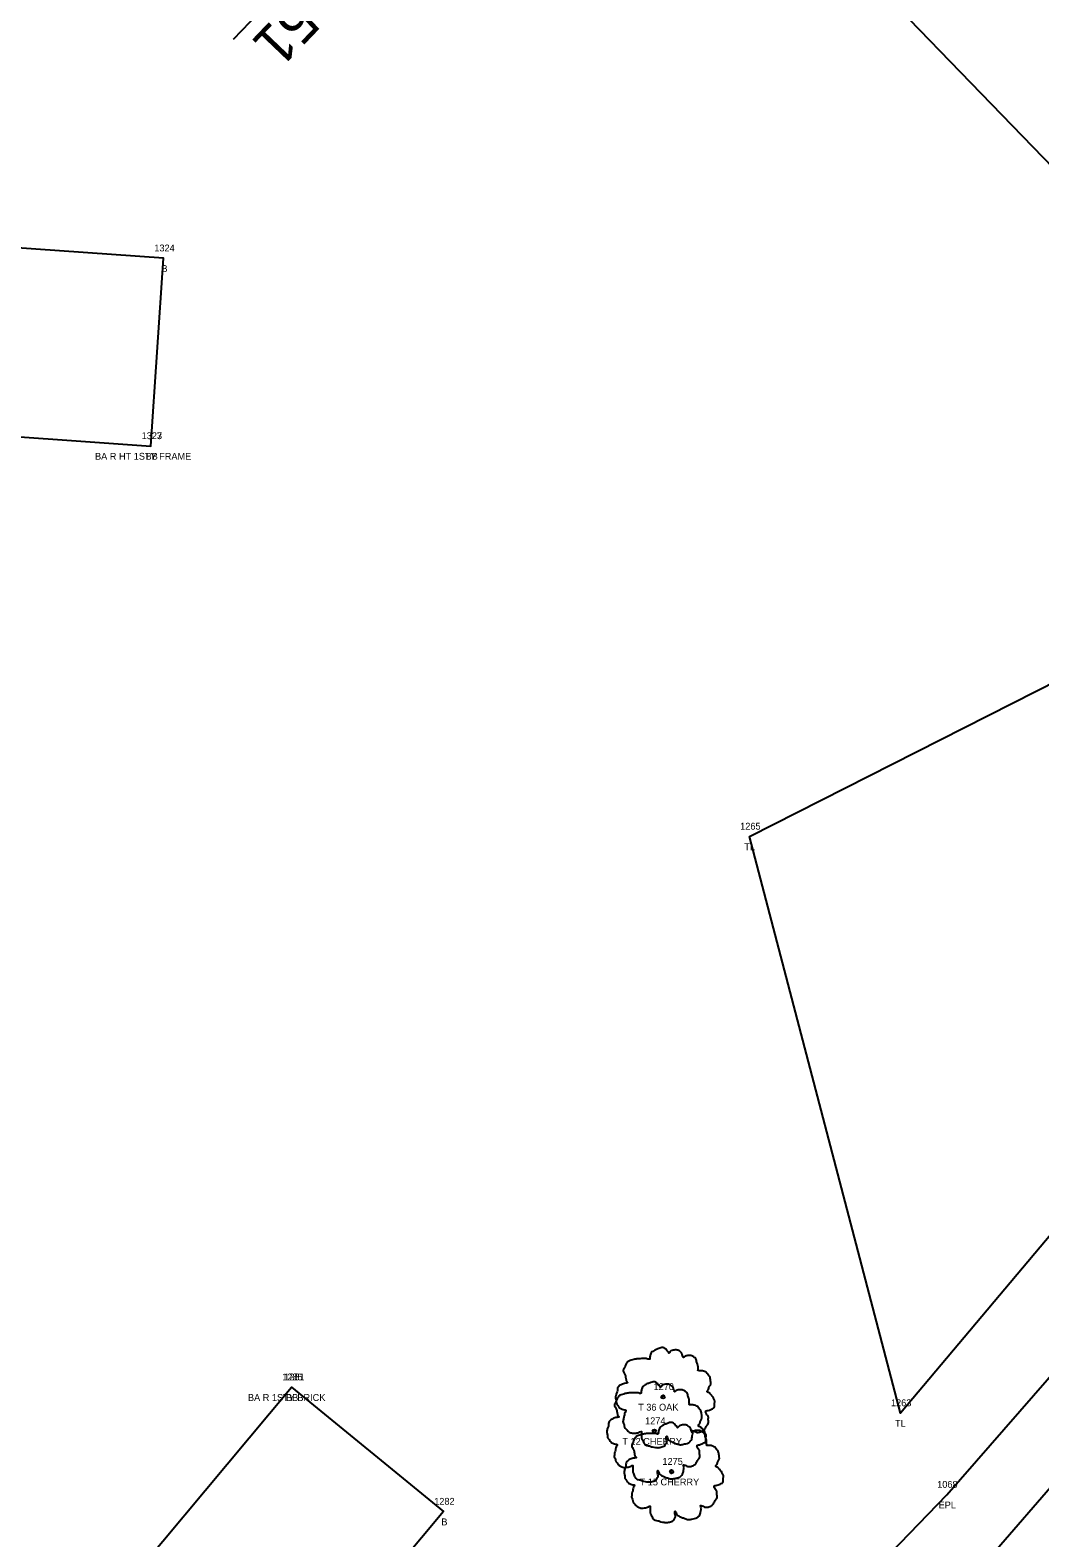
# Model space of a CAD drawing. Extents: x 1812340 to 1815011, y 1177659 to 1180159.
# Drawn here: x 1813776.3 to 1813923.6, y 1178289.1 to 1178509 of the extents above; entities that cross this region are included whole.
import ezdxf

# ---------------------------------------------------------------- set-up
doc = ezdxf.new("R2010")
doc.units = 0
for name, color, linetype in [('RD_EX_Bldg', 7, 'Continuous'), ('RD_EX_Bldg_txCode', 7, 'Continuous'), ('RD_EX_Road', 7, 'Continuous'), ('RD_EX_Road_txCode', 7, 'Continuous'), ('RD_EX_VEG', 7, 'Continuous'), ('RD_EX_VEG_txCode', 7, 'Continuous'), ('RD_HC_CL', 7, 'Continuous'), ('RD_HC_Data', 7, 'Continuous'), ('RD_SMD_Locator', 7, 'Continuous')]:
    doc.layers.add(name, color=color, linetype=linetype)

msp = doc.modelspace()

# ---------------------------------------------------------------- linework, layer by layer
at = {"layer": 'RD_EX_Bldg'}
for points in [[(1813793.91, 1178448.32), (1813795.75, 1178475.7), (1813735.04, 1178479.99), (1813733.19, 1178452.61), (1813793.91, 1178448.32)], [(1813814.41, 1178311.05), (1813836.59, 1178292.91), (1813805.22, 1178255.39), (1813783.05, 1178273.53), (1813814.41, 1178311.05)]]:
    msp.add_lwpolyline(points, dxfattribs=at)
at = {"layer": 'RD_EX_Road'}
msp.add_lwpolyline([(1813829.87, 1178208.6), (1813830.81, 1178209.56), (1813845.51, 1178227.94), (1813874.69, 1178258.74), (1813910.02, 1178295.38), (1813943.63, 1178333.84), (1813974.31, 1178373.09), (1814001.91, 1178410.56), (1814011.9, 1178425.95), (1814015.58, 1178434.3), (1814016.71, 1178442.08), (1814017.03, 1178447.13), (1814015.19, 1178453.67), (1813986.47, 1178480.85), (1813949.15, 1178515.86)], dxfattribs=at)
at = {"layer": 'RD_EX_VEG'}
for points in [[(1813964.65, 1178448.48), (1813984.61, 1178463.55), (1813943.71, 1178503.46), (1813904.65, 1178537.57), (1813863.79, 1178578.71), (1813833.99, 1178603.93), (1813823.24, 1178594.53), (1813964.65, 1178448.48)], [(1813961.33, 1178431.97), (1813986.04, 1178406.55), (1813953.31, 1178366.71), (1813903.24, 1178307.28), (1813881.24, 1178391.37), (1813961.33, 1178431.97)]]:
    msp.add_lwpolyline(points, dxfattribs=at)
for centre, radius in [((1813868.62, 1178309.64), 0.25), ((1813868.61, 1178309.62), 0.0001), ((1813867.35, 1178304.65), 0.25), ((1813867.34, 1178304.63), 0.0001), ((1813869.87, 1178298.73), 0.25), ((1813869.86, 1178298.71), 0.0001)]:
    msp.add_circle(centre, radius, dxfattribs=at)
for points in [[(1813868.75, 1178316.81), (1813868.45, 1178316.83), (1813868.13, 1178316.73), (1813867.88, 1178316.63), (1813867.65, 1178316.56), (1813867.43, 1178316.46), (1813867.13, 1178316.28), (1813866.9, 1178316.08), (1813866.78, 1178315.83), (1813866.73, 1178315.61), (1813866.68, 1178315.33), (1813866.68, 1178315.16), (1813866.55, 1178315.13), (1813866.4, 1178315.16), (1813866.15, 1178315.23), (1813865.9, 1178315.23), (1813865.65, 1178315.23), (1813865.3, 1178315.21), (1813864.95, 1178315.21), (1813864.68, 1178315.16), (1813864.35, 1178315.11), (1813863.98, 1178314.98), (1813863.63, 1178314.86), (1813863.33, 1178314.61), (1813863.08, 1178314.13), (1813862.96, 1178313.78), (1813862.81, 1178313.53), (1813862.96, 1178313.08), (1813863.13, 1178312.73), (1813863.15, 1178312.53), (1813863.23, 1178312.11), (1813863.33, 1178311.88), (1813863.45, 1178311.68), (1813863.38, 1178311.66), (1813863.01, 1178311.61), (1813862.71, 1178311.51), (1813862.28, 1178311.28), (1813862.06, 1178311.06), (1813861.96, 1178310.73), (1813861.93, 1178310.38), (1813861.83, 1178310.18), (1813861.76, 1178309.91), (1813861.73, 1178309.83), (1813861.68, 1178309.51), (1813861.78, 1178309.06), (1813861.81, 1178308.71), (1813861.93, 1178308.49), (1813862.08, 1178308.31), (1813862.26, 1178308.06), (1813862.66, 1178307.84), (1813862.98, 1178307.74), (1813863.18, 1178307.71), (1813863.01, 1178307.21), (1813862.96, 1178306.86), (1813862.83, 1178306.46), (1813862.83, 1178306.39), (1813862.78, 1178305.91), (1813862.93, 1178305.59), (1813863.01, 1178305.21), (1813863.18, 1178304.99), (1813863.45, 1178304.69), (1813863.78, 1178304.46), (1813864.28, 1178304.34), (1813864.68, 1178304.36), (1813865.25, 1178304.54), (1813865.5, 1178304.61), (1813865.48, 1178304.44), (1813865.5, 1178304.06), (1813865.5, 1178303.64), (1813865.65, 1178303.31), (1813865.75, 1178303.04), (1813865.9, 1178302.79), (1813866.23, 1178302.56), (1813866.63, 1178302.49), (1813867.05, 1178302.34), (1813867.5, 1178302.26), (1813868, 1178302.24), (1813868.6, 1178302.39), (1813868.88, 1178302.51), (1813868.98, 1178302.69), (1813869.18, 1178303.06), (1813869.13, 1178303.29), (1813869.15, 1178303.89), (1813869.25, 1178303.71), (1813869.43, 1178303.36), (1813869.93, 1178303.06), (1813870.33, 1178302.89), (1813870.8, 1178302.74), (1813871.1, 1178302.66), (1813871.58, 1178302.74), (1813871.95, 1178302.81), (1813872.33, 1178302.94), (1813872.63, 1178303.21), (1813872.8, 1178303.49), (1813872.85, 1178303.76), (1813872.93, 1178304.14), (1813872.98, 1178304.31)], [(1813872.98, 1178304.31), (1813872.9, 1178304.49), (1813872.85, 1178304.74), (1813872.93, 1178304.71), (1813873.1, 1178304.66), (1813873.38, 1178304.54), (1813873.6, 1178304.46), (1813873.93, 1178304.49), (1813874.2, 1178304.59), (1813874.65, 1178304.86), (1813874.92, 1178305.34), (1813875.2, 1178305.74), (1813875.27, 1178306.06), (1813875.22, 1178306.29), (1813875.2, 1178306.79), (1813875, 1178307.04), (1813874.95, 1178307.16), (1813874.85, 1178307.56), (1813874.92, 1178307.61), (1813875.2, 1178307.66), (1813875.57, 1178307.79), (1813875.85, 1178307.91), (1813876.07, 1178308.09), (1813876.15, 1178308.31), (1813876.12, 1178308.71), (1813876.17, 1178309.11), (1813876.1, 1178309.26), (1813876, 1178309.41), (1813875.92, 1178309.61), (1813875.77, 1178309.76), (1813875.67, 1178309.91), (1813875.57, 1178310.01), (1813875.45, 1178310.16), (1813875.27, 1178310.28), (1813875.12, 1178310.33), (1813875.07, 1178310.48), (1813875.22, 1178310.68), (1813875.27, 1178310.78), (1813875.3, 1178311.01), (1813875.52, 1178311.36), (1813875.57, 1178311.76), (1813875.52, 1178312.18), (1813875.47, 1178312.46), (1813875.32, 1178312.73), (1813875.12, 1178312.98), (1813875, 1178313.16), (1813874.82, 1178313.28), (1813874.5, 1178313.41), (1813874.25, 1178313.46), (1813873.9, 1178313.46), (1813873.7, 1178313.51), (1813873.73, 1178313.56), (1813873.73, 1178313.71), (1813873.73, 1178313.98), (1813873.65, 1178314.43), (1813873.5, 1178314.93), (1813873.5, 1178314.96), (1813873.4, 1178315.21), (1813873.18, 1178315.41), (1813873, 1178315.51), (1813872.8, 1178315.63), (1813872.55, 1178315.66), (1813872.25, 1178315.66), (1813871.98, 1178315.61), (1813871.78, 1178315.51), (1813871.6, 1178315.38), (1813871.53, 1178315.53), (1813871.43, 1178315.83), (1813871.38, 1178315.98), (1813871.23, 1178316.16), (1813871, 1178316.36), (1813870.55, 1178316.48), (1813869.93, 1178316.41), (1813869.63, 1178316.21), (1813869.48, 1178316.03), (1813869.43, 1178316.16), (1813869.23, 1178316.36), (1813869.13, 1178316.53), (1813868.95, 1178316.66), (1813868.8, 1178316.76), (1813868.7, 1178316.81)], [(1813867.48, 1178311.82), (1813867.18, 1178311.84), (1813866.86, 1178311.74), (1813866.61, 1178311.64), (1813866.38, 1178311.57), (1813866.16, 1178311.47), (1813865.86, 1178311.29), (1813865.63, 1178311.09), (1813865.51, 1178310.84), (1813865.46, 1178310.62), (1813865.41, 1178310.34), (1813865.41, 1178310.17), (1813865.28, 1178310.14), (1813865.13, 1178310.17), (1813864.88, 1178310.24), (1813864.63, 1178310.24), (1813864.38, 1178310.24), (1813864.03, 1178310.22), (1813863.68, 1178310.22), (1813863.41, 1178310.17), (1813863.08, 1178310.12), (1813862.71, 1178309.99), (1813862.36, 1178309.87), (1813862.06, 1178309.62), (1813861.81, 1178309.14), (1813861.68, 1178308.79), (1813861.53, 1178308.54), (1813861.68, 1178308.09), (1813861.86, 1178307.74), (1813861.88, 1178307.54), (1813861.96, 1178307.12), (1813862.06, 1178306.89), (1813862.18, 1178306.69), (1813862.11, 1178306.67), (1813861.73, 1178306.62), (1813861.43, 1178306.52), (1813861.01, 1178306.29), (1813860.78, 1178306.07), (1813860.68, 1178305.74), (1813860.66, 1178305.39), (1813860.56, 1178305.19), (1813860.48, 1178304.92), (1813860.46, 1178304.84), (1813860.41, 1178304.52), (1813860.51, 1178304.07), (1813860.53, 1178303.72), (1813860.66, 1178303.5), (1813860.81, 1178303.32), (1813860.98, 1178303.07), (1813861.38, 1178302.85), (1813861.71, 1178302.75), (1813861.91, 1178302.72), (1813861.73, 1178302.22), (1813861.68, 1178301.87), (1813861.56, 1178301.47), (1813861.56, 1178301.4), (1813861.51, 1178300.92), (1813861.66, 1178300.6), (1813861.73, 1178300.22), (1813861.91, 1178300), (1813862.18, 1178299.7), (1813862.51, 1178299.47), (1813863.01, 1178299.35), (1813863.41, 1178299.37), (1813863.98, 1178299.55), (1813864.23, 1178299.62), (1813864.21, 1178299.45), (1813864.23, 1178299.07), (1813864.23, 1178298.65), (1813864.38, 1178298.32), (1813864.48, 1178298.05), (1813864.63, 1178297.8), (1813864.96, 1178297.57), (1813865.36, 1178297.5), (1813865.78, 1178297.35), (1813866.23, 1178297.27), (1813866.73, 1178297.25), (1813867.33, 1178297.4), (1813867.61, 1178297.52), (1813867.71, 1178297.7), (1813867.91, 1178298.07), (1813867.86, 1178298.3), (1813867.88, 1178298.9), (1813867.98, 1178298.72), (1813868.15, 1178298.37), (1813868.65, 1178298.07), (1813869.05, 1178297.9), (1813869.53, 1178297.75), (1813869.83, 1178297.67), (1813870.3, 1178297.75), (1813870.68, 1178297.82), (1813871.05, 1178297.95), (1813871.35, 1178298.22), (1813871.53, 1178298.5), (1813871.58, 1178298.77), (1813871.65, 1178299.15), (1813871.7, 1178299.32)], [(1813871.7, 1178299.32), (1813871.63, 1178299.5), (1813871.58, 1178299.75), (1813871.65, 1178299.72), (1813871.83, 1178299.67), (1813872.1, 1178299.55), (1813872.33, 1178299.47), (1813872.65, 1178299.5), (1813872.93, 1178299.6), (1813873.38, 1178299.87), (1813873.65, 1178300.35), (1813873.93, 1178300.75), (1813874, 1178301.07), (1813873.95, 1178301.3), (1813873.93, 1178301.8), (1813873.73, 1178302.05), (1813873.68, 1178302.17), (1813873.58, 1178302.57), (1813873.65, 1178302.62), (1813873.93, 1178302.67), (1813874.3, 1178302.8), (1813874.58, 1178302.92), (1813874.8, 1178303.1), (1813874.88, 1178303.32), (1813874.85, 1178303.72), (1813874.9, 1178304.12), (1813874.83, 1178304.27), (1813874.73, 1178304.42), (1813874.65, 1178304.62), (1813874.5, 1178304.77), (1813874.4, 1178304.92), (1813874.3, 1178305.02), (1813874.18, 1178305.17), (1813874, 1178305.29), (1813873.85, 1178305.34), (1813873.8, 1178305.49), (1813873.95, 1178305.69), (1813874, 1178305.79), (1813874.03, 1178306.02), (1813874.25, 1178306.37), (1813874.3, 1178306.77), (1813874.25, 1178307.19), (1813874.2, 1178307.47), (1813874.05, 1178307.74), (1813873.85, 1178307.99), (1813873.73, 1178308.17), (1813873.55, 1178308.29), (1813873.23, 1178308.42), (1813872.98, 1178308.47), (1813872.63, 1178308.47), (1813872.43, 1178308.52), (1813872.45, 1178308.57), (1813872.45, 1178308.72), (1813872.45, 1178308.99), (1813872.38, 1178309.44), (1813872.23, 1178309.94), (1813872.23, 1178309.97), (1813872.13, 1178310.22), (1813871.9, 1178310.42), (1813871.73, 1178310.52), (1813871.53, 1178310.64), (1813871.28, 1178310.67), (1813870.98, 1178310.67), (1813870.7, 1178310.62), (1813870.5, 1178310.52), (1813870.33, 1178310.39), (1813870.25, 1178310.54), (1813870.15, 1178310.84), (1813870.1, 1178310.99), (1813869.95, 1178311.17), (1813869.73, 1178311.37), (1813869.28, 1178311.49), (1813868.65, 1178311.42), (1813868.35, 1178311.22), (1813868.2, 1178311.04), (1813868.15, 1178311.17), (1813867.95, 1178311.37), (1813867.86, 1178311.54), (1813867.68, 1178311.67), (1813867.53, 1178311.77), (1813867.43, 1178311.82)], [(1813870.01, 1178305.89), (1813869.71, 1178305.92), (1813869.38, 1178305.82), (1813869.13, 1178305.72), (1813868.91, 1178305.64), (1813868.68, 1178305.54), (1813868.38, 1178305.37), (1813868.16, 1178305.17), (1813868.03, 1178304.92), (1813867.98, 1178304.69), (1813867.93, 1178304.42), (1813867.93, 1178304.25), (1813867.81, 1178304.22), (1813867.66, 1178304.25), (1813867.41, 1178304.32), (1813867.16, 1178304.32), (1813866.91, 1178304.32), (1813866.56, 1178304.3), (1813866.21, 1178304.3), (1813865.93, 1178304.25), (1813865.61, 1178304.2), (1813865.23, 1178304.07), (1813864.88, 1178303.95), (1813864.58, 1178303.7), (1813864.33, 1178303.22), (1813864.21, 1178302.87), (1813864.06, 1178302.62), (1813864.21, 1178302.17), (1813864.38, 1178301.82), (1813864.41, 1178301.62), (1813864.48, 1178301.2), (1813864.58, 1178300.97), (1813864.71, 1178300.77), (1813864.63, 1178300.75), (1813864.26, 1178300.7), (1813863.96, 1178300.6), (1813863.53, 1178300.37), (1813863.31, 1178300.15), (1813863.21, 1178299.82), (1813863.18, 1178299.47), (1813863.08, 1178299.27), (1813863.01, 1178299), (1813862.98, 1178298.92), (1813862.93, 1178298.6), (1813863.03, 1178298.15), (1813863.06, 1178297.8), (1813863.18, 1178297.57), (1813863.33, 1178297.4), (1813863.51, 1178297.15), (1813863.91, 1178296.92), (1813864.23, 1178296.82), (1813864.43, 1178296.8), (1813864.26, 1178296.3), (1813864.21, 1178295.95), (1813864.08, 1178295.55), (1813864.08, 1178295.47), (1813864.03, 1178295), (1813864.18, 1178294.67), (1813864.26, 1178294.3), (1813864.43, 1178294.07), (1813864.71, 1178293.77), (1813865.03, 1178293.55), (1813865.53, 1178293.42), (1813865.93, 1178293.45), (1813866.51, 1178293.62), (1813866.76, 1178293.7), (1813866.73, 1178293.52), (1813866.76, 1178293.15), (1813866.76, 1178292.73), (1813866.91, 1178292.4), (1813867.01, 1178292.13), (1813867.16, 1178291.88), (1813867.48, 1178291.65), (1813867.88, 1178291.58), (1813868.31, 1178291.43), (1813868.76, 1178291.35), (1813869.26, 1178291.33), (1813869.86, 1178291.48), (1813870.13, 1178291.6), (1813870.23, 1178291.78), (1813870.43, 1178292.15), (1813870.38, 1178292.38), (1813870.41, 1178292.98), (1813870.51, 1178292.8), (1813870.68, 1178292.45), (1813871.18, 1178292.15), (1813871.58, 1178291.98), (1813872.05, 1178291.83), (1813872.35, 1178291.75), (1813872.83, 1178291.83), (1813873.2, 1178291.9), (1813873.58, 1178292.03), (1813873.88, 1178292.3), (1813874.05, 1178292.58), (1813874.1, 1178292.85), (1813874.18, 1178293.22), (1813874.23, 1178293.4)], [(1813874.23, 1178293.4), (1813874.15, 1178293.57), (1813874.1, 1178293.82), (1813874.18, 1178293.8), (1813874.35, 1178293.75), (1813874.63, 1178293.62), (1813874.85, 1178293.55), (1813875.18, 1178293.57), (1813875.45, 1178293.67), (1813875.9, 1178293.95), (1813876.18, 1178294.42), (1813876.45, 1178294.82), (1813876.53, 1178295.15), (1813876.48, 1178295.37), (1813876.45, 1178295.87), (1813876.25, 1178296.12), (1813876.2, 1178296.25), (1813876.1, 1178296.65), (1813876.18, 1178296.7), (1813876.45, 1178296.75), (1813876.83, 1178296.87), (1813877.1, 1178297), (1813877.33, 1178297.17), (1813877.4, 1178297.4), (1813877.38, 1178297.8), (1813877.43, 1178298.2), (1813877.35, 1178298.35), (1813877.25, 1178298.5), (1813877.18, 1178298.7), (1813877.03, 1178298.85), (1813876.93, 1178299), (1813876.83, 1178299.1), (1813876.7, 1178299.25), (1813876.53, 1178299.37), (1813876.38, 1178299.42), (1813876.33, 1178299.57), (1813876.48, 1178299.77), (1813876.53, 1178299.87), (1813876.55, 1178300.1), (1813876.78, 1178300.45), (1813876.83, 1178300.85), (1813876.78, 1178301.27), (1813876.73, 1178301.55), (1813876.58, 1178301.82), (1813876.38, 1178302.07), (1813876.25, 1178302.25), (1813876.08, 1178302.37), (1813875.75, 1178302.5), (1813875.5, 1178302.55), (1813875.15, 1178302.55), (1813874.95, 1178302.6), (1813874.98, 1178302.65), (1813874.98, 1178302.8), (1813874.98, 1178303.07), (1813874.9, 1178303.52), (1813874.75, 1178304.02), (1813874.75, 1178304.05), (1813874.65, 1178304.3), (1813874.43, 1178304.5), (1813874.25, 1178304.59), (1813874.05, 1178304.72), (1813873.8, 1178304.74), (1813873.5, 1178304.74), (1813873.23, 1178304.69), (1813873.03, 1178304.59), (1813872.85, 1178304.47), (1813872.78, 1178304.62), (1813872.68, 1178304.92), (1813872.63, 1178305.07), (1813872.48, 1178305.24), (1813872.25, 1178305.44), (1813871.8, 1178305.57), (1813871.18, 1178305.49), (1813870.88, 1178305.29), (1813870.73, 1178305.12), (1813870.68, 1178305.24), (1813870.48, 1178305.44), (1813870.38, 1178305.62), (1813870.21, 1178305.74), (1813870.06, 1178305.84), (1813869.96, 1178305.89)]]:
    msp.add_spline(points, degree=3, dxfattribs=at)
at = {"layer": 'RD_HC_CL'}
msp.add_line((1814048.02, 1178438.51), (1813851.74, 1178211.63), dxfattribs=at)
at = {"layer": 'RD_HC_Data'}
msp.add_line((1813886.05, 1178591.55), (1813805.93, 1178507.6), dxfattribs=at)
at = {"layer": 'RD_SMD_Locator'}
for centre in [(1813795.75, 1178475.7), (1813793.91, 1178448.32), (1813793.91, 1178448.32), (1813881.24, 1178391.37), (1813814.41, 1178311.05), (1813814.41, 1178311.05), (1813903.24, 1178307.28), (1813910.02, 1178295.38), (1813836.59, 1178292.91)]:
    msp.add_circle(centre, 0.001, dxfattribs=at)

# ---------------------------------------------------------------- texts
at = {"layer": 'RD_EX_Bldg_txCode'}
for s, p in [('1324', (1813794.41, 1178476.7)), ('B', (1813795.45, 1178473.7)), ('1323', (1813792.56, 1178449.32)), ('1327', (1813792.56, 1178449.32)), ('BA R HT 1STY FRAME', (1813785.76, 1178446.32)), ('BB', (1813793.13, 1178446.32)), ('1285', (1813813.07, 1178312.05)), ('1281', (1813813.35, 1178312.05)), ('BA R 1STY BRICK', (1813808.07, 1178309.05)), ('BB', (1813813.63, 1178309.05)), ('1282', (1813835.24, 1178293.91)), ('B', (1813836.28, 1178290.91))]:
    msp.add_text(s, height=1, dxfattribs=at).set_placement(p)
at = {"layer": 'RD_EX_Road_txCode'}
for s, p in [('1068', (1813908.61, 1178296.38)), ('EPL', (1813908.82, 1178293.38))]:
    msp.add_text(s, height=1, dxfattribs=at).set_placement(p)
at = {"layer": 'RD_EX_VEG_txCode'}
for s, p in [('1265', (1813879.87, 1178392.37)), ('TL', (1813880.47, 1178389.37)), ('1270', (1813867.23, 1178310.64)), ('T 36 OAK', (1813864.99, 1178307.64)), ('1263', (1813901.87, 1178308.28)), ('1274', (1813866, 1178305.65)), ('TL', (1813902.47, 1178305.28)), ('T 12 CHERRY', (1813862.68, 1178302.65)), ('1275', (1813868.53, 1178299.73)), ('T 15 CHERRY', (1813865.2, 1178296.73))]:
    msp.add_text(s, height=1, dxfattribs=at).set_placement(p)
at = {"layer": 'RD_HC_Data'}
msp.add_text('PC=12+48.51', height=6, rotation=226.3393, dxfattribs=at).set_placement((1813842.62, 1178543.15))

doc.saveas('drawing.dxf')
